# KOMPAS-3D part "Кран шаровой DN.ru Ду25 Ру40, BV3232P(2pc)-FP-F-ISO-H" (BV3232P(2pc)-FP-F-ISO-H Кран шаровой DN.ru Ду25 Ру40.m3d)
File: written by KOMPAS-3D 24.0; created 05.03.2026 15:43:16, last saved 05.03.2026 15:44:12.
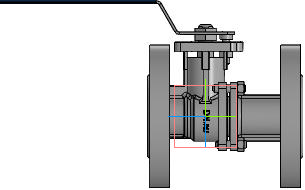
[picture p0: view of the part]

Document properties: Автор: R2D2; Полное имя файла: BV3232P(2pc)-FP-F-ISO-H Кран шаровой DN.ru Ду25 Ру40.cdw

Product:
- Part/product: Кран шаровой DN.ru Ду25 Ру40  | designation BV3232P(2pc)-FP-F-ISO-H
    Масса: 3.68
    Раздел спецификации: Прочие изделия
    Форматы листов документа: A2
    Примечание: D160-22131

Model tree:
1. Операция без истории:1

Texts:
  BV3232P(2pc)-FP-F-ISO-H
